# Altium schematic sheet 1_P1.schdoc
size 307 x 218 mm; Symbol: Drawing-Symbol_A4; Device: Drawing-Symbol_A4; @Project Name: jerve dave tagata; @Page Count: 1; @Update Date: 2026-05-29; @Create Date: 2026-05-22; @Schematic Name: Schematic1; @Page No: 1; @Page Name: P1; Company: EasyEDA.com; Version: V1.0; Page Size: A4; @Create Time: 17:40:28; @Update Time: 01:59:16; Width: 1170; Height: 825; Region Start: 1; X Region Count: 6; Y Region Count: 4; Blade Width: 10; Title Block Position: 3; @Board Name: PCB2
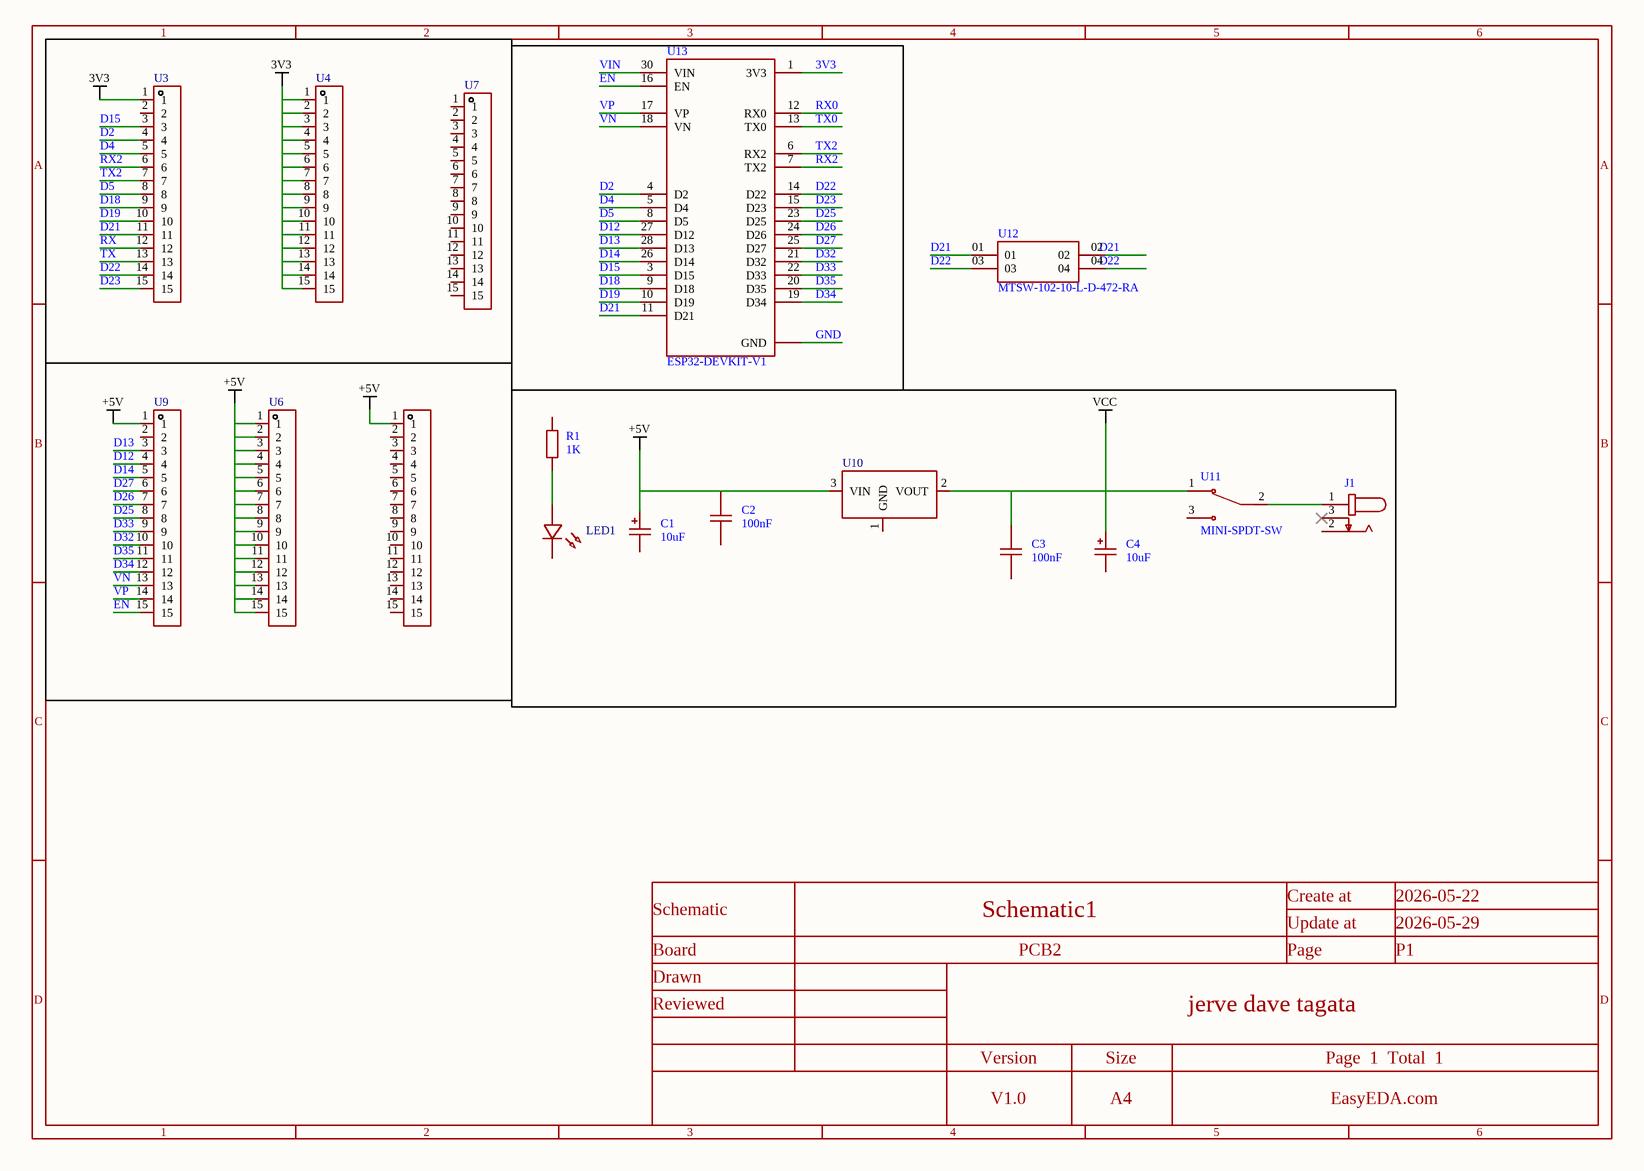
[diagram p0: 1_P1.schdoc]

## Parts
C1  10uF  [CAP-SMD_BD3.0-L3.3-W3.3-RD]
C2  100nF  [C0201]
C3  100nF  [C0201]
C4  10uF  [CAP-SMD_BD3.0-L3.3-W3.3-RD]
J1  (no value)  [GCT_DCJ200-10-A-XX-K_REVA]
LED1  (no value)  [LED0402-RD_YELLOW]
R1  1K  [R0603]
U3  (no value)  [HDR-TH_15P-P2.54-V-F-1]
U4  HX PM2.54-1x15P ZC  [HDR-TH_15P-P2.54-V-F-1]  (value not drawn)
U5  HX PM2.54-1x15P ZC  [HDR-TH_15P-P2.54-V-F-1]  (value not drawn)
U6  HX PM2.54-1x15P ZC  [HDR-TH_15P-P2.54-V-F-1]  (value not drawn)
U7  HX PM2.54-1x15P ZC  [HDR-TH_15P-P2.54-V-F-1]  (value not drawn)
U9  (no value)  [HDR-TH_15P-P2.54-V-F-1]
U10  AMS1117-5.0(XBLW)  [SOT-223-3_L6.5-W3.4-P2.30-LS7.0-BR-1]  (value not drawn)
U11  MINI-SPDT-SW  [SW_MINI-SPDT-SW]
U12  MTSW-102-10-L-D-472-RA  [SAMTEC_MTSW-102-10-L-D-472-RA]
U13  ESP32-DEVKIT-V1  [MODULE_ESP32_DEVKIT_V1]

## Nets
3V3: U3.1 U4.1 U4.2 U4.3 U4.4 U4.5 U4.6 U4.7 U4.8 U4.9 U4.10 U4.11 U4.12 U4.13 U4.14 U4.15 U13.1(3V3)
+5V: C1.1 C2.1 U5.1 U6.1 U6.2 U6.3 U6.4 U6.5 U6.6 U6.7 U6.8 U6.9 U6.10 U6.11 U6.12 U6.13 U6.14 U6.15 U9.1 U10.3(VIN)
VCC: C3.1 C4.1 U10.2(VOUT) U11.1
D2: U3.4 U13.4(D2)
D4: U3.5 U13.5(D4)
D5: U3.8 U13.8(D5)
D12: U9.4 U13.27(D12)
D13: U9.3 U13.28(D13)
D14: U9.5 U13.26(D14)
D15: U3.3 U13.3(D15)
D18: U3.9 U13.9(D18)
D19: U3.10 U13.10(D19)
D21: U3.11 U12.01 U13.11(D21)
D22: U3.14 U12.03 U13.14(D22)
D23: U3.15 U13.15(D23)
D25: U9.8 U13.23(D25)
D26: U9.7 U13.24(D26)
D27: U9.6 U13.25(D27)
D32: U9.10 U13.21(D32)
D33: U9.9 U13.22(D33)
D34: U9.12 U13.19(D34)
D35: U9.11 U13.20(D35)
EN: U9.15 U13.16(EN)
GND: U13.2*2(GND)
RX: U3.12
RX0: U13.12(RX0)
RX2: U3.6 U13.7(TX2)
TX: U3.13
TX0: U13.13(TX0)
TX2: U3.7 U13.6(RX2)
VIN: U13.30(VIN)
VN: U9.13 U13.18(VN)
VP: U9.14 U13.17(VP)
NetJ1_1: J1.1 U11.2
NetLED1_1: LED1.1(A) R1.1

Not connected (* = marked no-connect by the designer): C1 2; C2 2; C3 2; C4 2; J1 2 3*; LED1 2(C); R1 2; U3 2; U5 2 3 4 5 6 7 8 9 10 11 12 13 14 15; U7 1 2 3 4 5 6 7 8 9 10 11 12 13 14 15; U9 2; U10 1(GND); U11 3; U12 02 04

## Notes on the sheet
- Labels drawn without touching a wire or pin: D21, D22

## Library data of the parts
C1 C4 = C_Ele_SMD_3x5.4mm: Add into BOM: yes
C2 C3 = CAP_0201: Symbol: CAP; Convert to PCB: yes
J1 = DCJ200-10-A-XX-K_REVA: Add into BOM: yes
LED1 = LED_0402-R: Symbol: LED_R; Convert to PCB: yes
R1 = Res_0603: Symbol: Res; Convert to PCB: yes
U3-U7 U9 = HX PM2.54-1x15P ZC: Manufacturer: hanxia(韩下); Add into BOM: yes; Holes Structure: 1x15P; Pitch: 2.54mm; Circular Hole / Square Hole: Square Hole; Number of Positions: 15P; Current Rating: 3A; Voltage Rating (Max): 1kV; Holes Direction: Top; PIN Length: 3.2mm
U10 = AMS1117-5.0(XBLW)_C18723570: Manufacturer: XBLW(芯伯乐); Add into BOM: yes; Maximum Input Voltage: 15V; MAX Output Current: 1A
U11 = MINI-SPDT-SW: Add into BOM: yes
U12 = MTSW-102-10-L-D-472-RA: Add into BOM: yes
U13 = ESP32-DEVKIT-V1: Add into BOM: yes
